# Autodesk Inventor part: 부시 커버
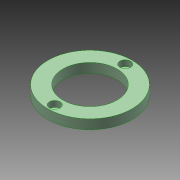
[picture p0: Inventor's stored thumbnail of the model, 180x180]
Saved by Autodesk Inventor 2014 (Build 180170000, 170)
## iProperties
Created: 2023-09
Part Number: 부시 커버
Material: 강철, 연강
Document SubType Name: Modeling
Designer: mdu-01
Density: 1 g/cm^3
Appearance: 기본값(1)
Author: mdu-01
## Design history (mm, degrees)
sketch "스케치1"
  geometry: C1 r 20 at (0, 0); C2 r 31 at (0, 0); 1 further point
  constraints: 2 centre point, 2 coincident
  dimensions: "d0" = 40 diameter of C1; "d1" = 62 diameter of C2
extrude "돌출1" new body sketch "스케치1" distance "d2" = 7; taper "d3" = 0 deg
sketch "스케치2"
  geometry: C1 r 22.5 at (0, 0); 2 further points
  constraints: 2 vertical alignment, 1 centre point, 1 coincident, 2 other
  dimensions: "d4" = 45 diameter of C1; "d6" = 3.5 dimension on C1
hole "구멍1" sketch "스케치2" at (0, 26) diameter "d7" = 4.5; stored, may be unused: countersink angle "d11" = 90 deg, drill point angle "d13" = 118 deg; dims "d8" = 6, "d9" = 8, "d10" = 4.4, "d12" = 8
node "솔리드1"
pattern_circular "원형 패턴1" dims angle "d15" = 360 deg
